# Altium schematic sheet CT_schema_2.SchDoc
size 313 x 200 mm
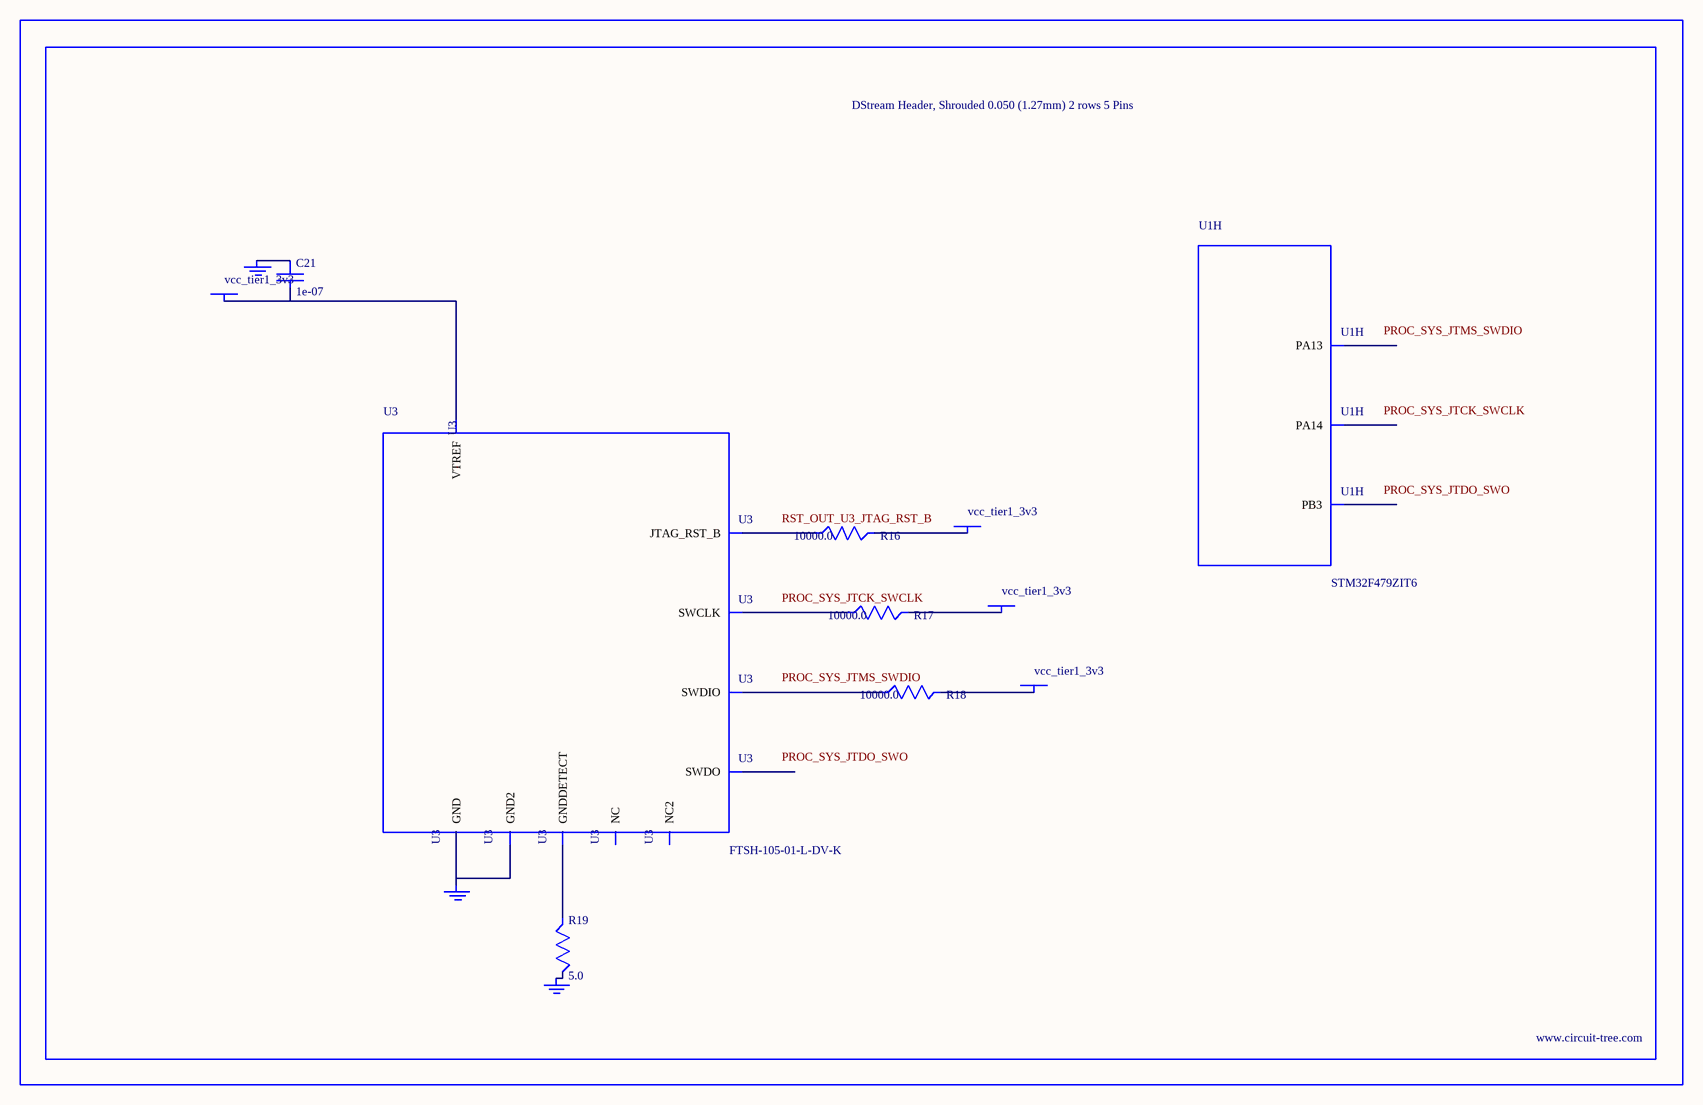
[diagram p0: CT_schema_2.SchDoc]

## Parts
BORDER1  (no value)
C21  1e-07  [C0402]
GND_INSTANCE_1_0  (no value)
GND_INSTANCE_1_1  (no value)
GND_INSTANCE_1_2  (no value)
POWER_INSTANCE_1_0  vcc_tier1_3v3
POWER_INSTANCE_1_1  vcc_tier1_3v3
POWER_INSTANCE_1_2  vcc_tier1_3v3
POWER_INSTANCE_1_3  vcc_tier1_3v3
R16  10000.0  [R0603]
R17  10000.0  [R0603]
R18  10000.0  [R0603]
R19  5.0  [R0603]
U1  STM32F479ZIT6  [LQFP144]  (part H of 13)
U3  FTSH-105-01-L-DV-K  [SAMTEC_FTSH-105-01-L-DV-K]

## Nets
NetC21_1: C21.1 GND_INSTANCE_1_0.0(GND)
NetC21_2: C21.2 POWER_INSTANCE_1_0.0(PWR) U3.1(VTREF)
NetGND_INSTANCE_1_1_0: GND_INSTANCE_1_1.0(GND) R19.2
NetGND_INSTANCE_1_2_0: GND_INSTANCE_1_2.0(GND) U3.3(GND) U3.5(GND2)
NetPOWER_INSTANCE_1_1_0: POWER_INSTANCE_1_1.0(PWR) R18.2
NetPOWER_INSTANCE_1_2_0: POWER_INSTANCE_1_2.0(PWR) R17.2
NetPOWER_INSTANCE_1_3_0: POWER_INSTANCE_1_3.0(PWR) R16.2
NetR16_1: R16.1 U3.10(JTAG_RST_B)
NetR17_1: R17.1 U3.4(SWCLK)
NetR18_1: R18.1 U3.2(SWDIO)
NetR19_1: R19.1 U3.9(GNDDETECT)

Not connected (* = marked no-connect by the designer): U1 107(PA13) 111(PA14) 132(PB3); U3 6(SWDO) 7(NC) 8(NC2)

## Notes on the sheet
- Labels drawn without touching a wire or pin: PROC_SYS_JTCK_SWCLK, PROC_SYS_JTDO_SWO, PROC_SYS_JTMS_SWDIO, RST_OUT_U3_JTAG_RST_B

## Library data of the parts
BORDER1 = BORDER_PAGE1
C21 = C0402C104K3RACTU
GND_INSTANCE_1_0-GND_INSTANCE_1_2 = GND
POWER_INSTANCE_1_0-POWER_INSTANCE_1_3 = PWR
R16-R18 = RC0603JR-0710KL
R19 = ERJ-3GEYJ5R1V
